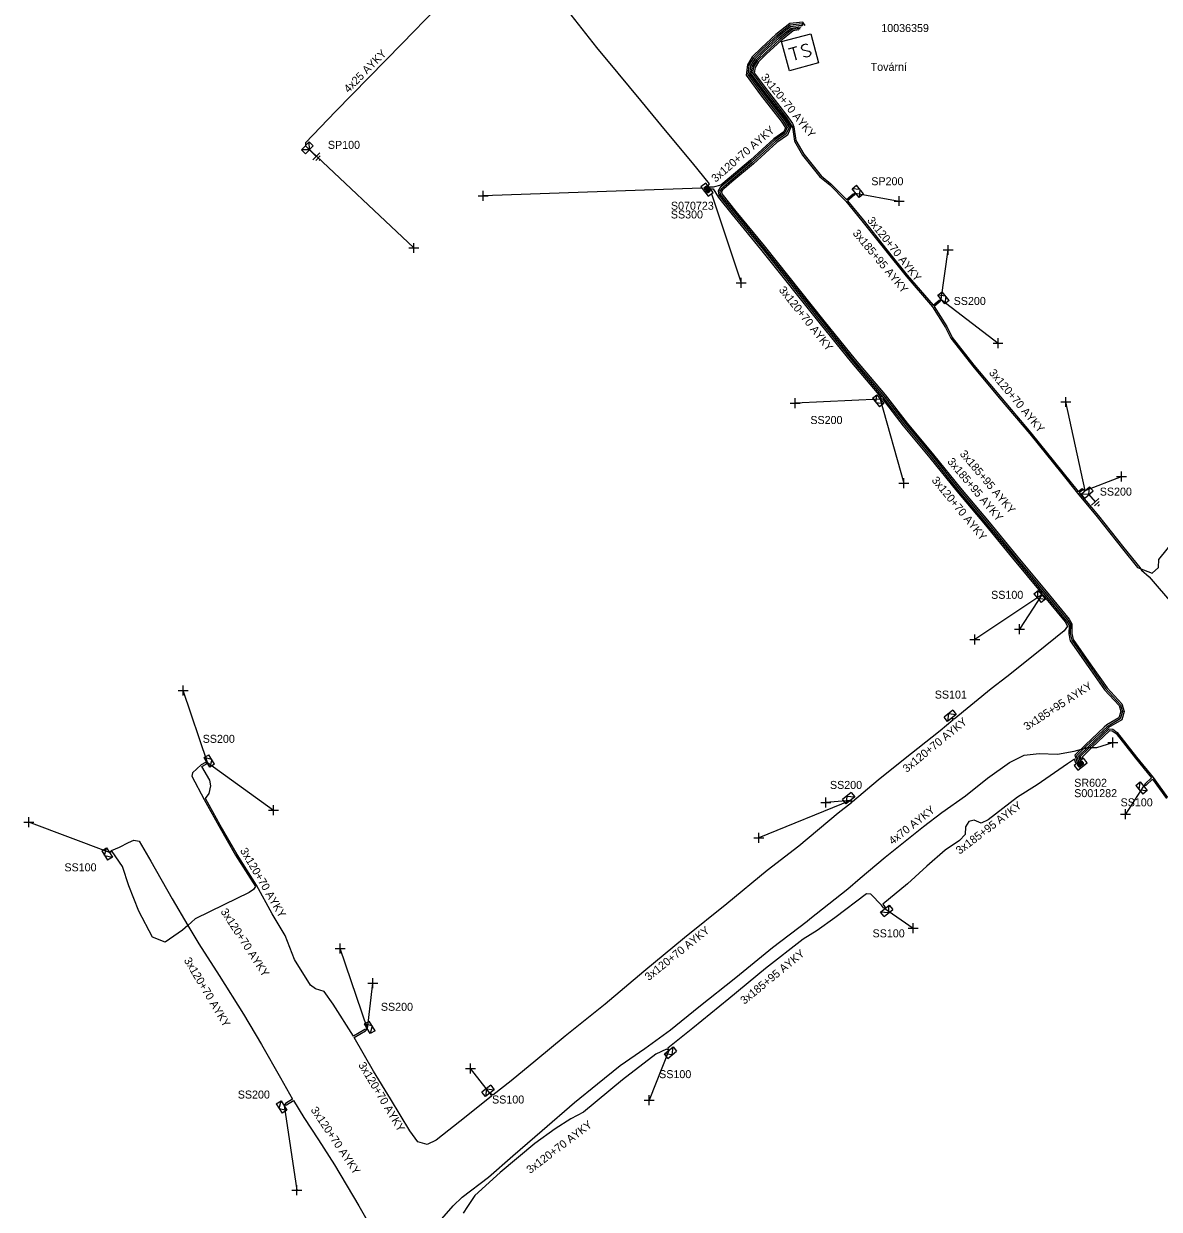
# Model space of a CAD drawing. Extents: x -763093 to -760976, y -1155572 to -1152009.
# Drawn here: x -762697.6 to -762555.8, y -1154837.4 to -1154689.2 of the extents above; entities that cross this region are included whole.
import ezdxf

# ---------------------------------------------------------------- set-up
doc = ezdxf.new("R2010")
doc.units = 0
for name, color, linetype in [('Vrstva 1', 7, 'Continuous'), ('Vrstva 14', 7, 'Continuous'), ('Vrstva 15', 7, 'Continuous'), ('Vrstva 25', 7, 'Continuous'), ('Vrstva 26', 7, 'Continuous'), ('Vrstva 27', 7, 'Continuous'), ('Vrstva 28', 7, 'Continuous'), ('Vrstva 29', 7, 'Continuous'), ('Vrstva 30', 7, 'Continuous'), ('Vrstva 31', 7, 'Continuous'), ('Vrstva 33', 7, 'Continuous'), ('Vrstva 34', 7, 'Continuous'), ('Vrstva 5', 7, 'Continuous'), ('Vrstva 59', 7, 'Continuous'), ('Vrstva 6', 7, 'Continuous'), ('Vrstva 8', 7, 'Continuous'), ('Vrstva 9', 7, 'Continuous')]:
    doc.layers.add(name, color=color, linetype=linetype)

# ---------------------------------------------------------------- blocks, each defined once
blk = doc.blocks.new('NN800')
at = {"layer": 'Vrstva 1'}
for points in [[(-0.44, 0.44), (0.44, -0.44)], [(-0.44, -0.44), (0.44, 0.44)]]:
    blk.add_lwpolyline(points, dxfattribs=at)
blk = doc.blocks.new('NN620')
at = {"layer": 'Vrstva 8'}
for points in [[(0.75, 0), (-0.75, 0)], [(-0.75, 0), (-0.75, -0.75)], [(0.75, -0.75), (0.75, 0)], [(-0.75, -0.75), (0.75, -0.75)], [(0.37, -0.18), (-0.38, -0.18)], [(-0.38, -0.18), (-0.38, -0.56)], [(-0.38, -0.56), (0.37, -0.56)], [(0.32, -0.23), (-0.33, -0.23)], [(-0.33, -0.23), (-0.33, -0.51)], [(-0.33, -0.51), (0.32, -0.51)], [(0.27, -0.27), (-0.28, -0.27)], [(-0.28, -0.27), (-0.28, -0.46)], [(-0.28, -0.46), (0.27, -0.46)], [(0.23, -0.32), (-0.23, -0.32)], [(-0.23, -0.32), (-0.23, -0.42)], [(-0.23, -0.42), (0.23, -0.42)], [(-0.19, -0.37), (0.19, -0.37)], [(0.23, -0.42), (0.23, -0.32)], [(0.27, -0.46), (0.27, -0.27)], [(0.32, -0.51), (0.32, -0.23)], [(0.37, -0.56), (0.37, -0.18)]]:
    blk.add_lwpolyline(points, dxfattribs=at)
blk = doc.blocks.new('NN630')
at = {"layer": 'Vrstva 9'}
for points in [[(0, -0.7), (-0.7, 0)], [(-0.7, -0.7), (-0.7, 0), (0.7, 0), (0.7, -0.7)], [(-0.7, -0.7), (0.7, -0.7)], [(0, -0.7), (0.7, 0)]]:
    blk.add_lwpolyline(points, dxfattribs=at)
blk = doc.blocks.new('NN810')
at = {"layer": 'Vrstva 14'}
for points in [[(0, -0.64), (0, -1.89)], [(0.63, -1.89), (-0.62, -1.89)], [(0.39, -2.2), (-0.4, -2.2)], [(0, -2.52), (-0.12, -2.52)], [(0.14, -2.52), (0, -2.52)]]:
    blk.add_lwpolyline(points, dxfattribs=at)
blk = doc.blocks.new('NN640')
at = {"layer": 'Vrstva 6'}
for points in [[(-1.89, 1.89), (1.89, 1.89)], [(-1.89, -1.89), (-1.89, 1.89)], [(1.89, 1.89), (1.89, -1.89)], [(-1.26, 0.79), (-0.22, 0.79)], [(-0.73, 0.79), (-0.73, -0.79)], [(1.2, 0.66), (0.94, 0.79), (0.66, 0.79), (0.41, 0.66), (0.28, 0.47), (0.28, 0.41), (0.41, 0.22), (1.13, -0.16), (1.26, -0.32), (1.26, -0.47), (1.13, -0.66), (0.91, -0.79), (0.63, -0.79), (0.5, -0.73), (0.28, -0.6)], [(1.89, -1.89), (-1.89, -1.89)]]:
    blk.add_lwpolyline(points, dxfattribs=at)

msp = doc.modelspace()

# ---------------------------------------------------------------- linework, layer by layer
at = {"layer": 'Vrstva 5'}
for points in [[(-762612.11, -1154709.48), (-762611.94, -1154709.23), (-762614.1, -1154706.59), (-762617.47, -1154702.57), (-762620.54, -1154698.81), (-762623.38, -1154695.38), (-762626.02, -1154692.18), (-762629.71, -1154687.53), (-762632.2, -1154684.19), (-762632.47, -1154683.46), (-762633.17, -1154682.96), (-762634.25, -1154682.74), (-762636.36, -1154682.22), (-762638.73, -1154681.94), (-762640.94, -1154682.27), (-762641.85, -1154683.11), (-762646.08, -1154687.29), (-762650.37, -1154691.71), (-762658.67, -1154700.2), (-762662.43, -1154704.09), (-762662.44, -1154704.48)], [(-762600.01, -1154689.43), (-762600.29, -1154689.02), (-762601.94, -1154689.18), (-762603.69, -1154690.57), (-762605.48, -1154692.23), (-762606.63, -1154693.35), (-762607.22, -1154694.34), (-762607.4, -1154695.63), (-762605.57, -1154698.11), (-762603.01, -1154701.39), (-762602.47, -1154702.23), (-762602.69, -1154702.73), (-762603.93, -1154703.61), (-762606.85, -1154706.27), (-762609.5, -1154708.51), (-762610.55, -1154709.38), (-762611.52, -1154709.64), (-762611.98, -1154709.63)], [(-762600.24, -1154689.44), (-762600.39, -1154689.23), (-762601.89, -1154689.4), (-762603.56, -1154690.72), (-762605.35, -1154692.37), (-762606.47, -1154693.47), (-762607.03, -1154694.41), (-762607.19, -1154695.58), (-762605.39, -1154698.01), (-762602.81, -1154701.31), (-762602.24, -1154702.21), (-762602.53, -1154702.86), (-762603.78, -1154703.74), (-762606.75, -1154706.44), (-762609.4, -1154708.69), (-762610.64, -1154709.71), (-762610.86, -1154710.11), (-762610.8, -1154710.63), (-762608.96, -1154712.95), (-762605.43, -1154717.25), (-762597.97, -1154726.6), (-762594.07, -1154731.43), (-762590.34, -1154735.84), (-762587.57, -1154739.39), (-762584.27, -1154743.35), (-762580.93, -1154747.53), (-762577.35, -1154751.76), (-762573.96, -1154755.88), (-762570.23, -1154760.39), (-762567.36, -1154763.88), (-762567.05, -1154764.43), (-762567.09, -1154765.48), (-762566.9, -1154766.35), (-762564.64, -1154769.55), (-762562.62, -1154772.47), (-762560.8, -1154774.44), (-762560.56, -1154775.17), (-762560.81, -1154775.98), (-762562.33, -1154776.86), (-762562.67, -1154777.13), (-762565, -1154779.35), (-762566.33, -1154780.66), (-762566.03, -1154781.54)], [(-762600.41, -1154689.56), (-762600.48, -1154689.45), (-762601.83, -1154689.61), (-762603.43, -1154690.87), (-762605.21, -1154692.52), (-762606.31, -1154693.6), (-762606.84, -1154694.48), (-762606.98, -1154695.53), (-762605.23, -1154697.89), (-762602.65, -1154701.2), (-762602.01, -1154702.19), (-762602.37, -1154703), (-762603.66, -1154703.9), (-762606.61, -1154706.6), (-762609.28, -1154708.85), (-762610.48, -1154709.84), (-762610.65, -1154710.15), (-762610.61, -1154710.56), (-762608.8, -1154712.83), (-762605.27, -1154717.13), (-762597.81, -1154726.48), (-762593.91, -1154731.31), (-762590.18, -1154735.72), (-762587.41, -1154739.27), (-762584.11, -1154743.23), (-762580.77, -1154747.41), (-762577.19, -1154751.64), (-762573.8, -1154755.76), (-762570.07, -1154760.27), (-762567.2, -1154763.76), (-762566.85, -1154764.32), (-762566.89, -1154765.45), (-762566.71, -1154766.27), (-762564.48, -1154769.44), (-762562.46, -1154772.34), (-762560.62, -1154774.34), (-762560.35, -1154775.17), (-762560.64, -1154776.1), (-762562.3, -1154777.09), (-762564.9, -1154779.52), (-762566.1, -1154780.72), (-762565.86, -1154781.41)], [(-762600.55, -1154689.7), (-762600.59, -1154689.65), (-762601.77, -1154689.81), (-762603.29, -1154691.03), (-762605.07, -1154692.66), (-762606.15, -1154693.72), (-762606.64, -1154694.54), (-762606.78, -1154695.47), (-762605.07, -1154697.77), (-762602.49, -1154701.08), (-762601.79, -1154702.17), (-762602.21, -1154703.13), (-762603.53, -1154704.05), (-762606.48, -1154706.75), (-762609.15, -1154709), (-762610.18, -1154709.85), (-762610.33, -1154709.97), (-762610.44, -1154710.19), (-762610.42, -1154710.48), (-762608.65, -1154712.7), (-762605.12, -1154717), (-762597.66, -1154726.35), (-762593.76, -1154731.18), (-762590.03, -1154735.59), (-762587.26, -1154739.14), (-762583.96, -1154743.1), (-762580.62, -1154747.28), (-762577.04, -1154751.51), (-762573.65, -1154755.63), (-762569.92, -1154760.14), (-762567.03, -1154763.65), (-762566.68, -1154764.21), (-762566.69, -1154765.42), (-762566.52, -1154766.19), (-762564.32, -1154769.33), (-762562.3, -1154772.21), (-762560.44, -1154774.24), (-762560.14, -1154775.17), (-762560.47, -1154776.22), (-762562.12, -1154777.18), (-762564.76, -1154779.67), (-762565.87, -1154780.77), (-762565.7, -1154781.28)], [(-762600.64, -1154689.92), (-762600.71, -1154689.82), (-762601.64, -1154689.96), (-762603.16, -1154691.18), (-762604.93, -1154692.81), (-762605.99, -1154693.85), (-762606.45, -1154694.61), (-762606.57, -1154695.42), (-762604.91, -1154697.65), (-762602.33, -1154700.97), (-762601.61, -1154702.15), (-762601.36, -1154703.88), (-762600.35, -1154705.63), (-762598.16, -1154708.37), (-762596.93, -1154709.36), (-762594.95, -1154711.4), (-762592.92, -1154713.87), (-762589.95, -1154717.61), (-762587.41, -1154720.76), (-762584.1, -1154724.62), (-762582.5, -1154727.18), (-762581.82, -1154728.53), (-762579.08, -1154732.02), (-762575.77, -1154735.97), (-762571.96, -1154740.47), (-762567.95, -1154745.45), (-762566.01, -1154747.89), (-762563.54, -1154750.85), (-762560.38, -1154754.84), (-762558.48, -1154757.18), (-762558.29, -1154757.26), (-762556.68, -1154757.9), (-762555.86, -1154757.2), (-762555.82, -1154756.17), (-762553.9, -1154753.81)], [(-762600.8, -1154690.04), (-762600.83, -1154689.99), (-762601.51, -1154690.12), (-762603.06, -1154691.35), (-762604.83, -1154692.98), (-762605.83, -1154693.97), (-762606.26, -1154694.68), (-762606.36, -1154695.37), (-762604.75, -1154697.53), (-762602.16, -1154700.85), (-762601.61, -1154701.71), (-762601.42, -1154702.1), (-762601.18, -1154703.8), (-762600.19, -1154705.51), (-762598.02, -1154708.23), (-762596.79, -1154709.22), (-762594.86, -1154711.2), (-762594.02, -1154710.5), (-762593.72, -1154710.39), (-762593.89, -1154710.66), (-762594.73, -1154711.35), (-762592.76, -1154713.75), (-762589.79, -1154717.49), (-762587.25, -1154720.64), (-762584.01, -1154724.41), (-762583.27, -1154723.79), (-762583, -1154723.7), (-762583.13, -1154723.95), (-762583.89, -1154724.57), (-762582.32, -1154727.08), (-762581.63, -1154728.43), (-762578.92, -1154731.9), (-762575.61, -1154735.85), (-762571.8, -1154740.35), (-762565.91, -1154747.69), (-762565.39, -1154747.32), (-762565.02, -1154747.55), (-762565.35, -1154747.54), (-762565.78, -1154747.85), (-762563.38, -1154750.73), (-762560.22, -1154754.72), (-762558.21, -1154757.2), (-762558, -1154757.52), (-762557.04, -1154758.36), (-762553.99, -1154761.88)], [(-762611.81, -1154709.84), (-762611.52, -1154709.84), (-762610.82, -1154710.93), (-762609.11, -1154713.08), (-762605.58, -1154717.38), (-762598.12, -1154726.73), (-762594.22, -1154731.56), (-762590.54, -1154735.91), (-762590.63, -1154736.14), (-762590.41, -1154736.07), (-762587.75, -1154739.49), (-762584.42, -1154743.48), (-762581.08, -1154747.66), (-762577.5, -1154751.89), (-762574.11, -1154756.01), (-762570.44, -1154760.45), (-762570.45, -1154760.59), (-762570.31, -1154760.6), (-762567.53, -1154763.99), (-762567.22, -1154764.53), (-762567.67, -1154765.11), (-762571.11, -1154767.9), (-762574.8, -1154770.83), (-762576.79, -1154772.36), (-762581.39, -1154776.13), (-762581.67, -1154775.99), (-762581.55, -1154776.25), (-762583.14, -1154777.58), (-762587.71, -1154781.24), (-762590.87, -1154783.78), (-762594.08, -1154786.48), (-762594.35, -1154786.29), (-762594.24, -1154786.6), (-762595.88, -1154787.88), (-762600.81, -1154792.02), (-762604.74, -1154795.04), (-762609.8, -1154799.24), (-762615.09, -1154803.49), (-762620.16, -1154807.67), (-762625, -1154811.75), (-762630.01, -1154815.78), (-762633.66, -1154818.79), (-762636.74, -1154821.35), (-762639.04, -1154823.14), (-762639.4, -1154822.88), (-762639.2, -1154823.26), (-762642.36, -1154825.79), (-762646.12, -1154828.77), (-762647.21, -1154829.29), (-762648.39, -1154828.97), (-762649.4, -1154827.6), (-762651.82, -1154823.6), (-762653.92, -1154820.15), (-762656.34, -1154815.93), (-762654.92, -1154815.09), (-762654.7, -1154814.84), (-762655, -1154814.91), (-762656.44, -1154815.76), (-762658.95, -1154811.75), (-762660.08, -1154810.17), (-762661.18, -1154809.85), (-762661.82, -1154809.39), (-762663.79, -1154806.17), (-762664.98, -1154803.16), (-762666.59, -1154800.46), (-762668.55, -1154796.9), (-762670.98, -1154793.04), (-762673.08, -1154789.37), (-762674.91, -1154786.06), (-762674.46, -1154785.44), (-762674.26, -1154784.48), (-762674.36, -1154783.75), (-762675.37, -1154782.04), (-762674.83, -1154781.75), (-762674.65, -1154781.54), (-762674.9, -1154781.56), (-762675.47, -1154781.86), (-762676.56, -1154782.86), (-762676.64, -1154783.25), (-762675.07, -1154786.2), (-762673.26, -1154789.47), (-762671.16, -1154793.14), (-762668.69, -1154797.05), (-762668.91, -1154797.43), (-762669.48, -1154797.82), (-762672.64, -1154799.36), (-762676.22, -1154801.09), (-762677.14, -1154801.92)], [(-762565.53, -1154781.16), (-762565.64, -1154780.82), (-762564.62, -1154779.82), (-762562.03, -1154777.36), (-762561.59, -1154777.4), (-762561.02, -1154777.8), (-762558.6, -1154780.89), (-762556.53, -1154783.44), (-762554.73, -1154785.94)], [(-762565.36, -1154781.03), (-762565.41, -1154780.88), (-762564.19, -1154779.68), (-762561.96, -1154777.57), (-762561.67, -1154777.6), (-762561.16, -1154777.94), (-762558.76, -1154781.01), (-762556.73, -1154783.48), (-762557.55, -1154784.22), (-762557.73, -1154784.52), (-762557.43, -1154784.41), (-762556.61, -1154783.64), (-762554.89, -1154786.06)], [(-762645.4, -1154838.58), (-762643.97, -1154836.98), (-762642.86, -1154835.87), (-762639.58, -1154833.39), (-762636.54, -1154830.71), (-762632.86, -1154827.56), (-762628.84, -1154824.04), (-762625.95, -1154821.73), (-762623.13, -1154819.41), (-762620.02, -1154817.29), (-762616.84, -1154814.98), (-762613.29, -1154812.11), (-762608.68, -1154808.41), (-762604.09, -1154804.67), (-762599.78, -1154801.39), (-762599.42, -1154801.1), (-762594.68, -1154797.33), (-762593.15, -1154796.02), (-762590, -1154793.38), (-762585.21, -1154789.57), (-762582.94, -1154787.82), (-762579.99, -1154785.71), (-762577.22, -1154783.51), (-762574.49, -1154781.55), (-762572.65, -1154780.63), (-762570.79, -1154780.45), (-762568.49, -1154780.52), (-762566.42, -1154780.15), (-762564.76, -1154779.67), (-762563.59, -1154779.69)], [(-762566.2, -1154781.66), (-762566.36, -1154781.15), (-762567.22, -1154781.73), (-762571.02, -1154784.33), (-762573.47, -1154785.89), (-762577.14, -1154788.74), (-762578.02, -1154789.12), (-762578.91, -1154788.75), (-762579.55, -1154788.93), (-762579.97, -1154789.61), (-762580.03, -1154790.54), (-762580.71, -1154791.31), (-762582.51, -1154792.5), (-762584.8, -1154794.52), (-762587.24, -1154796.72), (-762590.3, -1154799.28), (-762590.07, -1154799.59), (-762590.04, -1154799.81), (-762590.24, -1154799.71), (-762590.46, -1154799.4), (-762591.81, -1154798.03), (-762592.35, -1154797.99), (-762596.32, -1154800.99), (-762598.49, -1154802.57), (-762600.27, -1154803.64), (-762604.96, -1154807.3), (-762609.53, -1154811.11), (-762614.05, -1154814.78), (-762617.15, -1154817.28), (-762617.05, -1154817.55)], [(-762677.14, -1154801.92), (-762677.78, -1154802.51), (-762679.96, -1154804.03), (-762681.55, -1154803.37), (-762683.25, -1154800.14), (-762684.51, -1154796.96), (-762685.27, -1154794.55), (-762686.57, -1154792.7), (-762686.92, -1154792.81), (-762686.68, -1154792.54), (-762685.68, -1154792.13), (-762684.55, -1154791.57), (-762683.85, -1154791.25), (-762683.22, -1154791.4), (-762681.74, -1154793.89), (-762679.08, -1154798.59), (-762677.14, -1154801.92), (-762677.14, -1154801.92)], [(-762677.14, -1154801.92), (-762675.76, -1154804.21), (-762673.22, -1154808.16), (-762670.17, -1154813), (-762667.94, -1154816.82), (-762665.53, -1154820.95), (-762664.04, -1154823.63), (-762664.91, -1154824.18), (-762665.11, -1154824.43), (-762664.8, -1154824.35), (-762663.94, -1154823.81), (-762662.65, -1154825.93), (-762660.82, -1154828.7), (-762658.79, -1154831.85), (-762655.78, -1154836.95), (-762653.37, -1154841.13), (-762652.4, -1154843.39), (-762651.72, -1154844.97), (-762651.56, -1154846.3), (-762651.71, -1154846.97), (-762652.16, -1154847.24)], [(-762617.05, -1154817.55), (-762617.32, -1154817.38), (-762618.66, -1154818.03), (-762622.84, -1154821.24), (-762627.68, -1154825.26), (-762629.28, -1154826.11), (-762631.24, -1154827.33), (-762633.76, -1154829.19), (-762638.09, -1154832.8), (-762641.28, -1154835.69), (-762642.17, -1154837.04), (-762642.72, -1154837.89)]]:
    msp.add_lwpolyline(points, dxfattribs=at)
at = {"layer": 'Vrstva 59'}
for points in [[(-762662.44, -1154704.48), (-762648.88, -1154717.25)], [(-762612.97, -1154709.77), (-762640.25, -1154710.75)], [(-762611.72, -1154710.5), (-762608.02, -1154721.61)], [(-762593.72, -1154710.39), (-762588.25, -1154711.38)], [(-762583, -1154723.7), (-762582.13, -1154717.5)], [(-762583, -1154723.7), (-762575.92, -1154729.16)], [(-762590.63, -1154736.14), (-762601.25, -1154736.63)], [(-762590.63, -1154736.14), (-762587.67, -1154746.63)], [(-762565.02, -1154747.55), (-762567.44, -1154736.5)], [(-762565.02, -1154747.55), (-762560.48, -1154745.82)], [(-762570.45, -1154760.59), (-762578.8, -1154766.17)], [(-762570.45, -1154760.59), (-762573.25, -1154764.88)], [(-762674.65, -1154781.54), (-762677.71, -1154772.56)], [(-762563.59, -1154779.69), (-762561.58, -1154779.04)], [(-762674.65, -1154781.54), (-762666.44, -1154787.5)], [(-762557.73, -1154784.52), (-762560, -1154788)], [(-762594.35, -1154786.29), (-762605.78, -1154790.99)], [(-762594.35, -1154786.29), (-762597.43, -1154786.57)], [(-762686.92, -1154792.81), (-762697, -1154789)], [(-762590.04, -1154799.81), (-762586.5, -1154802.25)], [(-762654.7, -1154814.84), (-762658.11, -1154804.79)], [(-762654.7, -1154814.84), (-762654, -1154809.13)], [(-762617.05, -1154817.55), (-762619.5, -1154823.75)], [(-762639.4, -1154822.88), (-762641.82, -1154819.79)], [(-762665.11, -1154824.43), (-762663.5, -1154835)]]:
    msp.add_lwpolyline(points, dxfattribs=at)

# ---------------------------------------------------------------- block references
at = {"layer": 'Vrstva 15'}
for p, rotation in [((-762662.44, -1154704.48), 45.76471387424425), ((-762565.02, -1154747.55), 40.9815805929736)]:
    msp.add_blockref('NN810', p, dxfattribs=dict(at, rotation=rotation))
at = {"layer": 'Vrstva 25', "rotation": 14.999999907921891}
msp.add_blockref('NN640', (-762600.65, -1154692.79), dxfattribs=at)
at = {"layer": 'Vrstva 28'}
for p, rotation in [((-762611.98, -1154709.73), -52.41311516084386), ((-762565.82, -1154781.47), 36.972761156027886)]:
    msp.add_blockref('NN620', p, dxfattribs=dict(at, rotation=rotation))
at = {"layer": 'Vrstva 31'}
for p, rotation in [((-762662.44, -1154704.48), 45.76471382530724), ((-762593.72, -1154710.39), 128.50177775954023), ((-762583, -1154723.7), 128.64668606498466), ((-762590.63, -1154736.14), -50.81182782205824), ((-762565.02, -1154747.55), 40.9815805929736), ((-762570.45, -1154760.59), -50.655897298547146), ((-762581.67, -1154775.99), -140.7191932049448), ((-762674.74, -1154781.54), 120.61463334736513), ((-762557.73, -1154784.52), -50.77709165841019), ((-762594.35, -1154786.29), -140.79845551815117), ((-762686.92, -1154792.81), -58.081991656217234), ((-762590.04, -1154799.81), 38.9896915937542), ((-762654.7, -1154814.84), 120.64645830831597), ((-762617.05, -1154817.55), 38.99937787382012), ((-762639.4, -1154822.88), -141.98848891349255), ((-762665.11, -1154824.43), -58.198363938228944)]:
    msp.add_blockref('NN630', p, dxfattribs=dict(at, rotation=rotation))
at = {"layer": 'Vrstva 34'}
for p, rotation in [((-762640.25, -1154710.75), 45), ((-762588.25, -1154711.38), 45), ((-762648.88, -1154717.25), 45), ((-762582.13, -1154717.5), 45), ((-762608.02, -1154721.61), 44.99999995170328), ((-762575.92, -1154729.16), 45), ((-762601.25, -1154736.63), 45), ((-762567.44, -1154736.5), 44.99999995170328), ((-762560.48, -1154745.82), 45), ((-762587.67, -1154746.63), 44.99999995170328), ((-762573.25, -1154764.88), 45), ((-762578.8, -1154766.17), 45), ((-762677.71, -1154772.56), 45), ((-762561.58, -1154779.04), 45.00000009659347), ((-762666.44, -1154787.5), 44.99999995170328), ((-762597.43, -1154786.57), 44.99999995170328), ((-762697, -1154789), 45), ((-762560, -1154788), 45), ((-762605.78, -1154790.99), 45.000000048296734), ((-762586.5, -1154802.25), 45), ((-762658.11, -1154804.79), 45), ((-762654, -1154809.13), 45), ((-762641.82, -1154819.79), 45), ((-762619.5, -1154823.75), 45), ((-762663.5, -1154835), 45)]:
    msp.add_blockref('NN800', p, dxfattribs=dict(at, rotation=rotation))

# ---------------------------------------------------------------- texts
at = {"layer": 'Vrstva 26'}
msp.add_text('10036359', height=1, dxfattribs=at).set_placement((-762590.5, -1154690.26))
at = {"layer": 'Vrstva 27'}
msp.add_text('Tovární', height=1, dxfattribs=at).set_placement((-762591.83, -1154695.11))
at = {"layer": 'Vrstva 29'}
for s, p in [('S070723', (-762616.78, -1154712.47)), ('S001282', (-762566.4, -1154785.89))]:
    msp.add_text(s, height=1, dxfattribs=at).set_placement(p)
at = {"layer": 'Vrstva 30'}
for s, p in [('SS300', (-762616.79, -1154713.56)), ('SR602', (-762566.4, -1154784.59))]:
    msp.add_text(s, height=1, dxfattribs=at).set_placement(p)
at = {"layer": 'Vrstva 33'}
for s, p in [('SP100', (-762659.63, -1154704.86)), ('SP200', (-762591.75, -1154709.41)), ('SS200', (-762581.46, -1154724.37)), ('SS200', (-762599.36, -1154739.25)), ('SS200', (-762563.21, -1154748.2)), ('SS100', (-762576.78, -1154761.1)), ('SS101', (-762583.82, -1154773.57)), ('SS200', (-762675.27, -1154779.1)), ('SS200', (-762596.91, -1154784.86)), ('SS100', (-762560.61, -1154787.04)), ('SS100', (-762692.54, -1154795.16)), ('SS100', (-762591.59, -1154803.41)), ('SS200', (-762653.01, -1154812.59)), ('SS100', (-762618.25, -1154821.01)), ('SS200', (-762670.89, -1154823.56)), ('SS100', (-762639.12, -1154824.18))]:
    msp.add_text(s, height=1, dxfattribs=at).set_placement(p)
at = {"layer": 'Vrstva 6'}
for s, rotation, p in [('4x25 AYKY', 45.463, (-762657.04, -1154697.92)), ('3x120+70 AYKY', 309.096, (-762605.6, -1154695.93)), ('3x120+70 AYKY', 40.778, (-762611.2, -1154709.1)), ('3x120+70 AYKY', 308.466, (-762592.32, -1154713.82)), ('3x185+95 AYKY', 309.914, (-762594.14, -1154715.44)), ('3x120+70 AYKY', 308.486, (-762603.35, -1154722.52)), ('3x120+70 AYKY', 309.914, (-762577.11, -1154732.88)), ('3x185+95 AYKY', 310.076, (-762580.76, -1154743.02)), ('3x185+95 AYKY', 310.079, (-762582.31, -1154743.98)), ('3x120+70 AYKY', 309.468, (-762584.27, -1154746.31)), ('3x185+95 AYKY', 32.97, (-762572.32, -1154777.59)), ('3x120+70 AYKY', 39.233, (-762587.33, -1154782.87)), ('4x70 AYKY', 38.086, (-762589.09, -1154791.89)), ('3x185+95 AYKY', 37.191, (-762580.71, -1154793.09)), ('3x120+70 AYKY', 300.387, (-762670.64, -1154792.57)), ('3x120+70 AYKY', 302.962, (-762673.08, -1154800.19)), ('3x120+70 AYKY', 38.66, (-762619.55, -1154808.88)), ('3x185+95 AYKY', 39.243, (-762607.61, -1154811.85)), ('3x120+70 AYKY', 300.837, (-762677.66, -1154806.28)), ('3x120+70 AYKY', 300.935, (-762655.87, -1154819.36)), ('3x120+70 AYKY', 303.837, (-762661.82, -1154824.98)), ('3x120+70 AYKY', 37.299, (-762634.36, -1154833))]:
    msp.add_text(s, height=1, rotation=rotation, dxfattribs=at).set_placement(p)

doc.saveas('drawing.dxf')
